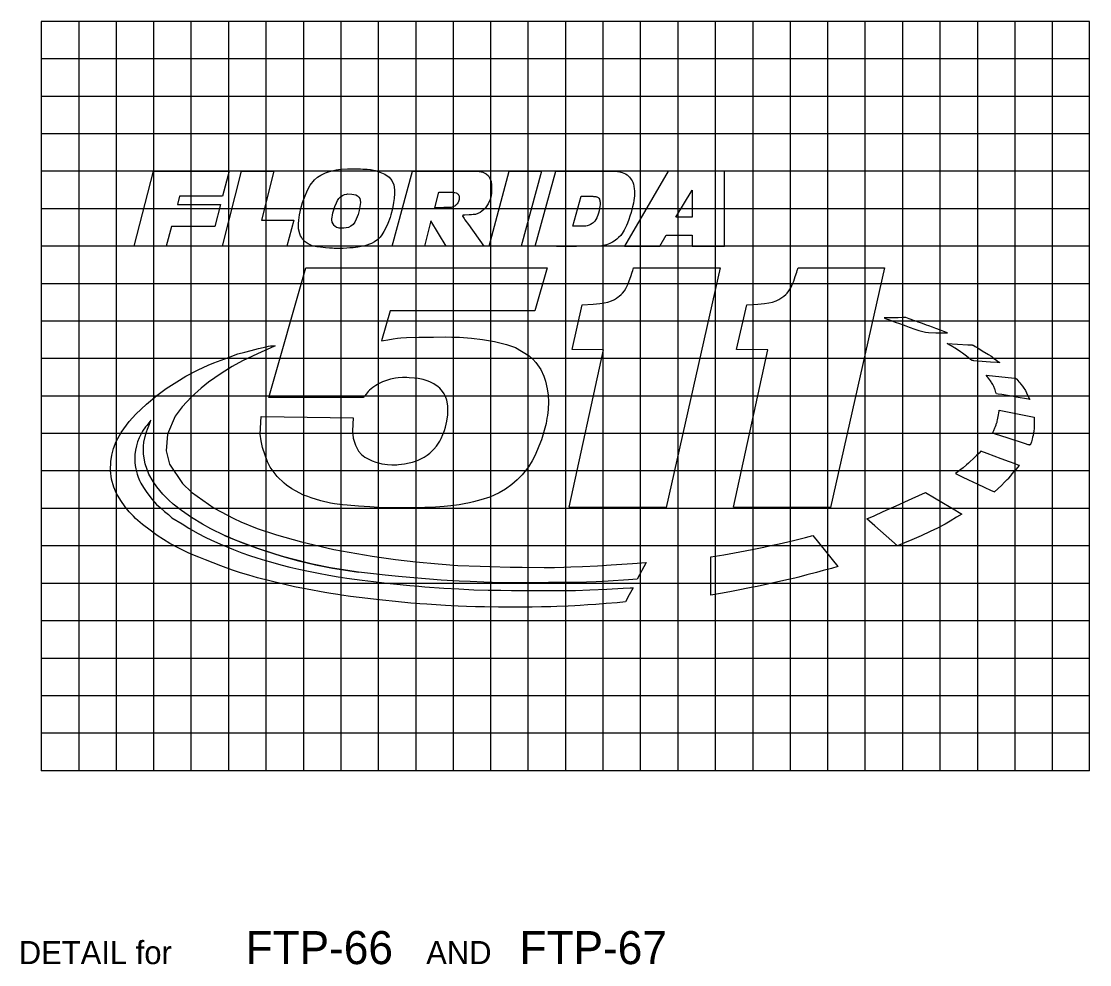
# Model space of a CAD drawing. Extents: x 0 to 770, y 0 to 495.
# Drawn here: x 591.8 to 753.4, y 337.2 to 479.8 of the extents above; entities that cross this region are included whole.
import ezdxf

# ---------------------------------------------------------------- set-up
doc = ezdxf.new("R2010")
doc.units = 0
doc.layers.add('Default', color=7, linetype='Continuous')

msp = doc.modelspace()

# ---------------------------------------------------------------- linework, layer by layer
at = {"layer": 'Default'}
for p, q in [((594.8, 479.79), (594.8, 366.49)), ((753.41, 479.79), (594.8, 479.79)), ((600.47, 479.79), (600.47, 366.49)), ((606.13, 479.79), (606.13, 366.49)), ((611.8, 479.79), (611.8, 366.49)), ((617.45, 479.79), (617.45, 366.49)), ((623.12, 479.79), (623.12, 366.49)), ((628.79, 479.79), (628.79, 366.49)), ((634.46, 479.79), (634.46, 366.49)), ((640.11, 479.79), (640.11, 366.49)), ((645.78, 479.79), (645.78, 366.49)), ((651.45, 479.79), (651.45, 366.49)), ((657.12, 479.79), (657.12, 366.49)), ((662.77, 479.79), (662.77, 366.49)), ((668.44, 479.79), (668.44, 366.49)), ((674.1, 479.79), (674.1, 366.49)), ((679.77, 479.79), (679.77, 366.49)), ((685.43, 479.79), (685.43, 366.49)), ((691.09, 479.79), (691.09, 366.49)), ((696.77, 479.79), (696.77, 366.49)), ((702.43, 479.79), (702.43, 366.49)), ((708.09, 479.79), (708.09, 366.49)), ((713.75, 479.79), (713.75, 366.49)), ((719.42, 479.79), (719.42, 366.49)), ((725.08, 479.79), (725.08, 366.49)), ((730.75, 479.79), (730.75, 366.49)), ((736.42, 479.79), (736.42, 366.49)), ((742.07, 479.79), (742.07, 366.49)), ((747.75, 479.79), (747.75, 366.49)), ((753.41, 366.49), (753.41, 479.79)), ((753.41, 474.12), (594.8, 474.12)), ((753.41, 468.45), (594.8, 468.45)), ((753.41, 462.79), (594.8, 462.79)), ((753.41, 457.12), (594.8, 457.12)), ((650.95, 457.12), (660.67, 457.12)), ((753.41, 451.46), (594.8, 451.46)), ((753.41, 445.8), (594.8, 445.8)), ((629.24, 422.92), (634.83, 442.52)), ((722.37, 442.52), (714.21, 406.3)), ((753.41, 440.13), (594.8, 440.13)), ((753.41, 434.47), (594.8, 434.47)), ((699.54, 406.36), (704.72, 430.11)), ((753.41, 428.81), (594.8, 428.81)), ((753.41, 423.13), (594.8, 423.13)), ((753.41, 417.48), (594.8, 417.48)), ((753.41, 411.82), (594.8, 411.82)), ((753.41, 406.14), (594.8, 406.14)), ((753.41, 400.48), (594.8, 400.48)), ((753.41, 394.82), (594.8, 394.82)), ((753.41, 389.15), (594.8, 389.15)), ((753.41, 383.48), (594.8, 383.48)), ((753.41, 377.82), (594.8, 377.82)), ((753.41, 372.15), (594.8, 372.15)), ((753.41, 366.49), (594.8, 366.49))]:
    msp.add_line(p, q, dxfattribs=at)
for points in [[(643.43, 457.47), (644.1, 457.43), (644.61, 457.37), (645.3, 457.24), (646.05, 457.01), (646.76, 456.71), (647.44, 456.22), (647.83, 455.73), (648.14, 455.06), (648.25, 454.33), (648.24, 453.77), (648.18, 452.99), (648.1, 452.41), (647.92, 451.43), (647.68, 450.53), (647.57, 450.13), (647.24, 449.23), (646.95, 448.59), (646.63, 448), (646.33, 447.51), (646.06, 447.17), (645.56, 446.7), (645.2, 446.45), (644.77, 446.23), (643.75, 445.85), (643.75, 445.85), (642.69, 445.65), (642.01, 445.57), (641.51, 445.53), (641.02, 445.49), (640.48, 445.47), (640.48, 445.47), (639.68, 445.46), (639.14, 445.47), (638.88, 445.48), (638.43, 445.5), (638.43, 445.5), (637.82, 445.54), (637.82, 445.54), (637.05, 445.63), (636.51, 445.7), (636.23, 445.74), (635.81, 445.85), (635.17, 446.14), (635.17, 446.14), (634.72, 446.46), (634.72, 446.46), (634.32, 446.88), (634.16, 447.15), (634.04, 447.39), (633.93, 447.65), (633.74, 448.4), (633.71, 449.17), (633.75, 449.74), (633.86, 450.52), (633.95, 451), (634.06, 451.48), (634.33, 452.4), (634.61, 453.16), (635.09, 454.25), (635.51, 455.02), (636.16, 455.85), (636.61, 456.23), (637.08, 456.53), (637.81, 456.89), (638.42, 457.11), (639.4, 457.34), (640.12, 457.43), (641.12, 457.5), (642.05, 457.52), (643.11, 457.49)], [(611.8, 457.12), (623.25, 457.12), (622.23, 453.36), (615.73, 453.36), (615.43, 452.11), (621.93, 452.11), (621.04, 448.79), (614.5, 448.79), (613.72, 445.79), (608.87, 445.79)], [(625.08, 457.12), (630, 457.12), (628.1, 449.71), (633, 449.71), (631.98, 445.79), (622.2, 445.79)], [(660.67, 457.12), (661.06, 457.1), (661.6, 456.99), (662.11, 456.75), (662.45, 456.45), (662.74, 455.94), (662.86, 455.58), (662.93, 455.09), (662.9, 453.87), (662.86, 453.41), (662.72, 452.85), (662.42, 452.18), (662.42, 452.18), (662.01, 451.6), (661.71, 451.29), (661.21, 450.91), (661.21, 450.91), (660.5, 450.61), (660.16, 450.57), (659.9, 450.55), (659.55, 450.52), (659.55, 450.52), (658.9, 450.48), (658.69, 450.48), (658.6, 450.48), (658.6, 450.46), (658.58, 450.41), (658.57, 450.41), (658.55, 450.39), (658.55, 450.34), (658.59, 450.28), (658.7, 450.12), (658.8, 449.97), (658.91, 449.81), (659.42, 449.1), (661.77, 445.79), (656.08, 445.79), (653.75, 449.65), (652.77, 445.79), (647.88, 445.79), (650.95, 457.12)], [(665.6, 457.12), (670.47, 457.12), (667.4, 445.79), (662.59, 445.79)], [(669.54, 445.79), (672.63, 457.12), (676.65, 457.16), (679.66, 457.15), (681.78, 457.12), (681.96, 457.11), (682.05, 457.1), (682.17, 457.08), (682.34, 457.05), (682.49, 457.01), (682.7, 456.94), (682.93, 456.85), (683.17, 456.73), (683.42, 456.58), (683.52, 456.51), (683.69, 456.36), (683.81, 456.24), (683.96, 456.05), (684.06, 455.9), (684.18, 455.69), (684.29, 455.47), (684.38, 455.19), (684.46, 454.85), (684.52, 454.45), (684.55, 454.17), (684.55, 453.58), (684.53, 453.41), (684.5, 453.05), (684.45, 452.7), (684.39, 452.32), (684.26, 451.73), (684.16, 451.34), (684.03, 450.91), (683.85, 450.32), (683.69, 449.83), (683.49, 449.27), (683.36, 448.93), (683.01, 448.21), (682.7, 447.73), (682.47, 447.42), (682.47, 447.42), (682.14, 447.09), (682.14, 447.09), (681.86, 446.85), (681.86, 446.85), (681.47, 446.57), (681.23, 446.42), (681.23, 446.42), (680.83, 446.22), (680.32, 446.03), (680.06, 445.95), (679.63, 445.86), (679.32, 445.82), (679, 445.8), (675.78, 445.76), (672.77, 445.75)], [(693.29, 445.79), (698.19, 445.79), (698.19, 457.12), (689.67, 457.12), (683.02, 445.79), (688.36, 445.79), (689.35, 447.48), (693.29, 447.48)], [(690.81, 450.2), (693.29, 454.27), (693.29, 450.2)], [(641.81, 453.69), (642.11, 453.63), (642.38, 453.55), (642.65, 453.43), (642.83, 453.23), (642.98, 452.99), (643.05, 452.76), (643.09, 452.41), (643.07, 452.1), (642.91, 451.21), (642.74, 450.61), (642.45, 449.88), (642.22, 449.45), (641.97, 449.1), (641.66, 448.81), (641.66, 448.81), (641.28, 448.64), (640.56, 448.51), (640.21, 448.5), (639.86, 448.53), (639.72, 448.56), (639.48, 448.65), (639.22, 448.84), (639.12, 448.94), (638.96, 449.16), (638.84, 449.42), (638.77, 449.76), (638.77, 449.94), (638.81, 450.21), (638.86, 450.47), (638.94, 450.83), (639.1, 451.43), (639.23, 451.82), (639.45, 452.37), (639.64, 452.73), (639.82, 452.99), (639.98, 453.17), (640.11, 453.3), (640.36, 453.47), (640.68, 453.61), (641.02, 453.69), (641.13, 453.7)], [(654.33, 451.62), (654.94, 453.96), (655.6, 453.99), (656.02, 453.99), (656.4, 453.99), (656.81, 453.98), (657.05, 453.96), (657.27, 453.94), (657.39, 453.92), (657.57, 453.87), (657.67, 453.82), (657.8, 453.74), (657.89, 453.66), (657.94, 453.59), (657.97, 453.53), (658.02, 453.38), (658.03, 453.3), (658.05, 453.2), (658.05, 453.07), (658.04, 452.93), (658.03, 452.84), (657.99, 452.69), (657.94, 452.57), (657.86, 452.42), (657.83, 452.38), (657.71, 452.21), (657.66, 452.14), (657.57, 452.05), (657.45, 451.93), (657.44, 451.93), (657.35, 451.86), (657.24, 451.79), (657.18, 451.76), (657.08, 451.72), (657.08, 451.72), (656.95, 451.69), (656.83, 451.67), (656.69, 451.66), (656.61, 451.65), (656.55, 451.64), (656.44, 451.64), (656.35, 451.64), (655.7, 451.63), (654.88, 451.62)], [(676.49, 453.36), (676.82, 453.37), (677.24, 453.37), (677.48, 453.37), (677.66, 453.37), (677.86, 453.37), (678.12, 453.36), (678.24, 453.35), (678.37, 453.33), (678.58, 453.31), (678.71, 453.29), (678.8, 453.28), (678.87, 453.26), (678.97, 453.22), (679.07, 453.15), (679.15, 453.06), (679.24, 452.9), (679.25, 452.88), (679.3, 452.72), (679.32, 452.6), (679.34, 452.45), (679.35, 452.3), (679.34, 452.15), (679.34, 452.05), (679.32, 451.86), (679.26, 451.49), (679.19, 451.16), (679.09, 450.81), (679, 450.51), (678.9, 450.26), (678.83, 450.08), (678.7, 449.83), (678.53, 449.59), (678.29, 449.35), (678.16, 449.24), (677.9, 449.07), (677.71, 448.98), (677.55, 448.92), (677.37, 448.87), (677.18, 448.85), (676.99, 448.84), (676.5, 448.84), (676.02, 448.84), (675.63, 448.84), (675.24, 448.84)], [(671.35, 442.52), (669.48, 436.04), (647.59, 436.04), (646.28, 431.51), (646.56, 431.56), (647.26, 431.66), (648.02, 431.78), (648.71, 431.88), (649.21, 431.96), (650.07, 431.99), (651.95, 432.04), (654.14, 432.07), (656.01, 432.08), (656.92, 432.07), (658.09, 432.04), (659.89, 431.88), (661.58, 431.68), (663.35, 431.41), (665.19, 430.95), (666.55, 430.46), (666.55, 430.46), (668.63, 429.23), (669.17, 428.73), (669.64, 428.21), (670.36, 427.17), (670.85, 426.16), (671.11, 425.39), (671.35, 424.21), (671.47, 423.27), (671.52, 422.27), (671.48, 421.13), (671.38, 420.18), (671.31, 419.8), (671.18, 419), (670.81, 417.59), (670.47, 416.53), (670.1, 415.56), (669.52, 414.2), (669.07, 413.34), (668.5, 412.44), (668.17, 411.98), (667.56, 411.23), (666.8, 410.45), (666, 409.75), (665.05, 409.07), (664.1, 408.51), (663.34, 408.14), (662.68, 407.87), (661.33, 407.44), (660.19, 407.14), (659.6, 407), (658.79, 406.84), (658.03, 406.71), (656.76, 406.53), (655.77, 406.44), (654.47, 406.36), (652.85, 406.28), (651.32, 406.23), (651.32, 406.23), (647.17, 406.23), (646.48, 406.25), (646.48, 406.25), (644.53, 406.37), (644.53, 406.37), (642.81, 406.5), (641.07, 406.66), (640.38, 406.72), (639.15, 406.85), (638.58, 406.95), (637.12, 407.29), (635.63, 407.75), (635.13, 407.93), (634.5, 408.18), (633.25, 408.81), (632.73, 409.12), (631.93, 409.67), (631.57, 409.95), (630.5, 410.97), (630.5, 410.97), (629.45, 412.39), (629.02, 413.2), (629.02, 413.2), (628.29, 415.35), (628.06, 416.36), (627.94, 417.39), (628.08, 420.03), (641.99, 419.87), (641.99, 419.87), (641.88, 417.9), (642, 416.79), (642, 416.79), (642.22, 416.01), (642.34, 415.71), (642.82, 414.83), (643.26, 414.32), (643.51, 414.09), (643.78, 413.92), (644.46, 413.54), (644.85, 413.36), (645.43, 413.14), (645.83, 413.02), (646.33, 412.91), (646.78, 412.83), (647.2, 412.79), (647.86, 412.76), (648.61, 412.76), (648.87, 412.77), (649.74, 412.87), (650.46, 413.02), (650.98, 413.16), (651.57, 413.36), (651.85, 413.47), (652.71, 413.91), (653.17, 414.21), (653.57, 414.52), (653.88, 414.8), (654.19, 415.1), (654.59, 415.57), (654.91, 416.03), (655.09, 416.33), (655.3, 416.72), (655.3, 416.72), (655.81, 417.91), (655.97, 418.44), (656.17, 419.33), (656.3, 420.28), (656.33, 420.73), (656.33, 421.22), (656.3, 421.62), (656.21, 422.27), (656.15, 422.5), (655.96, 423.07), (655.76, 423.49), (655.52, 423.85), (655.1, 424.34), (654.85, 424.56), (654.21, 425.01), (653.6, 425.31), (653.19, 425.46), (652.59, 425.63), (651.84, 425.79), (651.27, 425.86), (650.45, 425.91), (650.09, 425.93), (649.48, 425.94), (648.78, 425.89), (648.42, 425.84), (647.62, 425.67), (647.06, 425.51), (646.45, 425.29), (645.93, 425.02), (645.43, 424.73), (644.98, 424.45), (644.47, 424.05), (644.27, 423.81), (643.97, 423.44), (643.75, 423.17), (643.67, 423.08), (643.62, 423.01), (643.6, 422.99), (643.57, 422.97), (643.54, 422.94), (643.5, 422.93), (643.44, 422.92), (643.41, 422.92), (643.35, 422.92), (643.3, 422.92), (629.24, 422.92), (634.83, 442.52)], [(676.66, 436.92), (678.32, 437.03), (679.32, 437.15), (679.98, 437.24), (680.54, 437.36), (681.08, 437.54), (681.42, 437.7), (681.52, 437.75), (681.83, 437.94), (682.1, 438.13), (682.24, 438.24), (682.56, 438.52), (682.75, 438.72), (683.03, 439.07), (683.23, 439.38), (683.36, 439.6), (683.59, 440.09), (683.76, 440.54), (683.99, 441.2), (684.22, 441.87), (684.3, 442.14), (684.42, 442.53), (697.49, 442.53), (689.33, 406.31), (674.66, 406.36), (679.84, 430.11), (675.1, 430.16)], [(701.54, 436.91), (703.2, 437.03), (704.2, 437.15), (704.86, 437.24), (705.42, 437.36), (705.96, 437.54), (706.3, 437.7), (706.4, 437.75), (706.71, 437.94), (706.98, 438.13), (707.12, 438.24), (707.44, 438.52), (707.63, 438.72), (707.91, 439.07), (708.11, 439.37), (708.24, 439.6), (708.47, 440.09), (708.64, 440.53), (708.87, 441.2), (709.1, 441.87), (709.18, 442.14), (709.3, 442.52), (722.37, 442.52), (714.21, 406.3), (699.54, 406.36), (704.72, 430.11), (699.98, 430.16)], [(731.83, 432.72), (731.88, 432.72), (731.37, 432.9), (730.82, 433.1), (730.14, 433.35), (729.61, 433.55), (729.08, 433.74), (728.75, 433.86), (728.13, 434.09), (727.83, 434.2), (727.47, 434.33), (727.16, 434.44), (726.78, 434.58), (726.39, 434.73), (726.09, 434.83), (725.83, 434.93), (725.62, 435.01), (725.13, 435), (724.44, 434.99), (723.25, 434.97), (722.32, 434.95), (722.63, 434.84), (723.12, 434.66), (724.01, 434.33), (724.62, 434.11), (725.2, 433.9), (725.61, 433.75), (726.1, 433.57), (726.98, 433.27), (727.58, 433.07), (727.95, 432.96), (728.36, 432.83), (728.56, 432.78), (729.04, 432.75), (730.13, 432.7), (730.63, 432.7), (731.03, 432.7), (731.31, 432.7), (731.56, 432.71), (731.75, 432.71)], [(629.47, 430.71), (630.17, 430.71), (629.42, 430.38), (628.2, 429.84), (626.78, 429.19), (625.24, 428.46), (623.7, 427.62), (622, 426.57), (620.13, 425.24), (618.98, 424.32), (617.51, 423), (616.1, 421.5), (615.06, 420.09), (613.88, 417.4), (613.71, 414.88), (614.23, 412.85), (616.16, 409.93), (617.54, 408.6), (620.98, 406.17), (623.96, 404.61), (625.02, 404.13), (627.49, 403.13), (630.37, 402.16), (634.16, 401.08), (639.09, 399.95), (644.87, 398.92), (648.4, 398.43), (651.47, 398.06), (654.86, 397.75), (657.82, 397.54), (661.21, 397.41), (662.66, 397.37), (665.76, 397.29), (667.56, 397.26), (670.89, 397.21), (672.44, 397.23), (673.88, 397.27), (674.92, 397.3), (676.69, 397.37), (678.93, 397.48), (681.03, 397.62), (682.63, 397.73), (684.24, 397.84), (686.3, 397.98), (684.95, 395.44), (683.67, 395.36), (680.58, 395.15), (678.73, 395.03), (677.27, 395), (675.32, 394.97), (674.17, 394.95), (672.66, 394.94), (671.55, 394.93), (668.77, 394.91), (665.82, 394.92), (664.34, 394.92), (661.78, 395), (659.68, 395.08), (658.03, 395.16), (655.31, 395.33), (653.56, 395.45), (650.58, 395.69), (648.85, 395.85), (646.83, 396.06), (645.52, 396.2), (642.8, 396.53), (641.51, 396.7), (638.54, 397.18), (635.85, 397.73), (632.47, 398.57), (631.14, 398.95), (630.05, 399.28), (627.59, 400.08), (626.19, 400.59), (624.21, 401.36), (624.21, 401.36), (622.66, 402.01), (622.54, 402.06), (620.44, 403.07), (619.18, 403.77), (617.52, 404.79), (616.02, 405.82), (614.76, 406.78), (614.09, 407.39), (613.21, 408.3), (613.21, 408.3), (612.31, 409.42), (611.76, 410.21), (611.09, 411.35), (610.51, 412.87), (610.26, 414.35), (610.26, 414.35), (610.26, 415.58), (610.33, 416.16), (610.51, 417.04), (610.72, 417.71), (610.88, 418.16), (611.16, 418.88), (611.4, 419.49), (611.06, 419.08), (610.76, 418.71), (610.6, 418.51), (610.13, 417.83), (609.85, 417.34), (609.6, 416.81), (609.37, 416.23), (609.2, 415.62), (609.05, 414.94), (608.98, 414.33), (608.95, 413.6), (608.97, 413.1), (609.01, 412.63), (609.1, 412.12), (609.19, 411.72), (609.3, 411.31), (609.45, 410.88), (609.69, 410.37), (609.89, 409.98), (610.25, 409.33), (610.67, 408.69), (611.07, 408.14), (611.57, 407.52), (612.26, 406.77), (612.77, 406.27), (613.43, 405.71), (614.06, 405.23), (614.55, 404.73), (616.11, 403.8), (617.14, 403.16), (618.45, 402.41), (619.68, 401.78), (620.45, 401.41), (621.93, 400.74), (623.02, 400.28), (623.89, 399.93), (625.14, 399.46), (626.33, 399.04), (627.41, 398.68), (628.75, 398.26), (629.48, 398.06), (631.04, 397.63), (632.43, 397.29), (633.76, 396.97), (634.98, 396.7), (636.75, 396.34), (638.29, 396.06), (639.73, 395.82), (641.05, 395.62), (643.36, 395.31), (645.05, 395.09), (647.07, 394.86), (648.1, 394.75), (650.57, 394.51), (651.91, 394.39), (652.85, 394.31), (655.73, 394.1), (657.96, 393.97), (660.27, 393.86), (662.41, 393.81), (664.33, 393.77), (665.95, 393.75), (668.56, 393.73), (669.32, 393.72), (670.66, 393.72), (672.66, 393.72), (674.11, 393.72), (675.64, 393.74), (677.79, 393.83), (680.37, 393.95), (682.82, 394.08), (683.88, 394.14), (684.33, 394.16), (684.13, 393.77), (683.77, 393.09), (683.21, 392.01), (681.92, 391.9), (680.29, 391.77), (678.68, 391.65), (677.47, 391.57), (676.35, 391.49), (675.53, 391.44), (674.54, 391.39), (672.82, 391.32), (671.88, 391.29), (670.47, 391.25), (669.08, 391.22), (667.46, 391.2), (665.63, 391.2), (664, 391.21), (661.88, 391.25), (660.5, 391.28), (659.15, 391.33), (657.89, 391.38), (656.84, 391.43), (655.96, 391.48), (654.57, 391.56), (653.13, 391.66), (652.1, 391.74), (650.7, 391.85), (648.4, 392.06), (646.43, 392.27), (645.07, 392.42), (642.91, 392.68), (641.58, 392.86), (640.21, 393.05), (639.69, 393.13), (638.6, 393.29), (637.7, 393.43), (635.02, 393.92), (633.12, 394.31), (631.65, 394.64), (629.39, 395.19), (627.54, 395.68), (626.23, 396.05), (624.93, 396.43), (623.76, 396.83), (621.96, 397.49), (619.64, 398.37), (618.66, 398.76), (617.98, 399.04), (617.01, 399.44), (615.5, 400.18), (614.24, 400.87), (612.33, 402.08), (611.26, 402.85), (610.13, 403.74), (609.08, 404.65), (608.76, 404.96), (608.1, 405.66), (607.48, 406.41), (606.82, 407.35), (606.2, 408.43), (605.79, 409.36), (605.44, 410.58), (605.27, 411.87), (605.31, 413.23), (605.47, 414.19), (605.74, 415.19), (606.15, 416.27), (606.89, 417.63), (608.11, 419.29), (609.13, 420.42), (610.71, 421.89), (612.31, 423.21), (613.72, 424.26), (615.3, 425.31), (616.68, 426.13), (618.55, 427.11), (620.08, 427.81), (620.92, 428.16), (623.15, 428.99), (624.56, 429.51), (625.6, 429.8), (626.55, 430.05), (627.67, 430.32), (628.82, 430.58), (629.19, 430.66)], [(731.84, 431.1), (733.41, 431.01), (734.96, 430.91), (735.5, 430.88), (735.6, 430.88), (735.63, 430.87), (735.67, 430.87), (735.69, 430.86), (735.72, 430.86), (735.75, 430.85), (735.77, 430.84), (735.81, 430.83), (735.84, 430.81), (735.88, 430.78), (735.91, 430.77), (736.09, 430.65), (736.62, 430.32), (737.15, 430), (738.11, 429.4), (738.44, 429.2), (738.6, 429.1), (738.88, 428.89), (739.38, 428.52), (739.63, 428.33), (739.83, 428.19), (739.78, 428.19), (739.69, 428.2), (739.55, 428.21), (739.44, 428.22), (738.41, 428.29), (737.75, 428.34), (735.88, 428.49), (735.78, 428.5), (735.68, 428.51), (735.64, 428.52), (735.56, 428.56), (735.52, 428.59), (735.44, 428.65), (735.4, 428.68), (734.78, 429.15), (734.16, 429.63), (733.89, 429.83), (733.54, 430.07), (733.26, 430.24), (733.07, 430.36), (732.87, 430.48), (732.72, 430.58), (732.47, 430.73), (732.26, 430.86), (732, 431.01), (731.93, 431.04), (731.87, 431.08)], [(737.77, 426.3), (742.05, 425.85), (742.06, 425.85), (742.08, 425.85), (742.09, 425.85), (742.1, 425.85), (742.11, 425.85), (742.13, 425.84), (742.15, 425.84), (742.17, 425.84), (742.18, 425.83), (742.2, 425.83), (742.22, 425.82), (742.23, 425.82), (742.24, 425.81), (742.26, 425.8), (742.27, 425.79), (742.3, 425.77), (742.31, 425.76), (742.33, 425.74), (742.4, 425.67), (742.55, 425.5), (742.72, 425.31), (742.86, 425.14), (743.02, 424.94), (743.24, 424.65), (743.35, 424.48), (743.69, 423.96), (744.03, 423.29), (744.36, 422.63), (744.15, 422.67), (743.53, 422.77), (742.9, 422.88), (742.27, 422.99), (741.87, 423.06), (740.96, 423.21), (740.14, 423.36), (739.57, 423.45), (739.3, 423.5), (739.24, 423.68), (739.1, 424.07), (739.07, 424.17), (739, 424.34), (738.96, 424.45), (738.91, 424.57), (738.82, 424.77), (738.75, 424.9), (738.66, 425.05), (738.58, 425.18), (738.51, 425.29), (738.41, 425.42), (738.26, 425.62), (738.09, 425.86), (737.94, 426.06)], [(739.74, 421.03), (745.02, 419.93), (745.02, 419.25), (745.02, 418.58), (744.99, 418.19), (744.95, 417.88), (744.84, 417.19), (744.77, 416.92), (744.7, 416.62), (744.61, 416.24), (744.51, 415.94), (744.51, 415.94), (744.47, 415.86), (744.45, 415.83), (744.43, 415.81), (744.41, 415.78), (744.38, 415.76), (744.37, 415.75), (744.37, 415.75), (744.36, 415.75), (744.35, 415.74), (744.34, 415.74), (744.33, 415.74), (744.31, 415.74), (744.3, 415.75), (744.26, 415.75), (744.21, 415.77), (744.16, 415.78), (744.13, 415.79), (743.69, 415.93), (740.93, 416.8), (739.16, 417.36), (738.73, 417.5), (738.71, 417.5), (738.74, 417.58), (738.8, 417.71), (738.9, 417.94), (739.07, 418.32), (739.18, 418.56), (739.26, 418.78), (739.34, 419.02), (739.37, 419.1), (739.4, 419.21), (739.43, 419.35), (739.46, 419.54), (739.56, 420.06), (739.71, 420.88)], [(739, 408.65), (740.06, 409.64), (740.54, 410.11), (740.95, 410.53), (741.16, 410.75), (741.46, 411.09), (741.71, 411.37), (742.01, 411.71), (742.33, 412.08), (742.55, 412.35), (742.78, 412.64), (742.59, 412.71), (742.15, 412.87), (741.29, 413.19), (740.03, 413.66), (737.91, 414.44), (736.94, 414.8), (736.68, 414.53), (736.28, 414.13), (735.81, 413.67), (735.33, 413.23), (735.08, 413), (734.78, 412.75), (734.26, 412.31), (733.9, 412.03), (733.47, 411.7), (733.1, 411.42), (734.14, 410.93), (735.09, 410.48), (736.38, 409.88), (737.56, 409.33), (738.42, 408.93)], [(728.56, 408.57), (731.31, 406.93), (732.14, 406.44), (733, 405.93), (733.66, 405.54), (734.07, 405.3), (733.26, 404.81), (732.31, 404.24), (731.53, 403.79), (730.38, 403.18), (729.29, 402.65), (727.9, 402.01), (726.51, 401.41), (725.41, 400.94), (724.35, 400.48), (720.91, 403.51), (719.72, 404.56), (720.8, 405.05), (722.16, 405.67), (723.77, 406.4), (724.58, 406.76), (725.44, 407.16), (726.58, 407.67), (727.59, 408.13)], [(711.55, 402.07), (713.44, 399.71), (714.46, 398.43), (715.33, 397.35), (714.34, 397.09), (713.07, 396.75), (712.07, 396.48), (710.62, 396.09), (710.62, 396.09), (709.39, 395.76), (708.83, 395.61), (707.86, 395.39), (706.69, 395.13), (704.66, 394.69), (703.12, 394.37), (702.2, 394.18), (699.98, 393.74), (698.95, 393.55), (697.58, 393.3), (696.12, 393.05), (696.12, 394.39), (696.12, 395.93), (696.12, 396.82), (696.12, 398.81), (696.12, 398.81), (698.07, 399.15), (698.07, 399.15), (701.3, 399.74), (702.62, 400), (704.14, 400.31), (705.18, 400.53), (706.46, 400.81), (708.39, 401.27), (710.41, 401.77)]]:
    msp.add_lwpolyline(points, close=True, dxfattribs=at)
msp.add_arc((651.91, 469.78), 73.81, 246.5524, 262.9043, dxfattribs=at)

# ---------------------------------------------------------------- texts
for s, height, p in [('FTP-66', 5, (625.72, 337.25)), ('FTP-67', 5, (667.16, 337.25)), ('  DETAIL for ', 3.5, (588.81, 337.25)), (' AND ', 3.5, (651.74, 337.25))]:
    msp.add_text(s, height=height, dxfattribs=at).set_placement(p)

doc.saveas('drawing.dxf')
